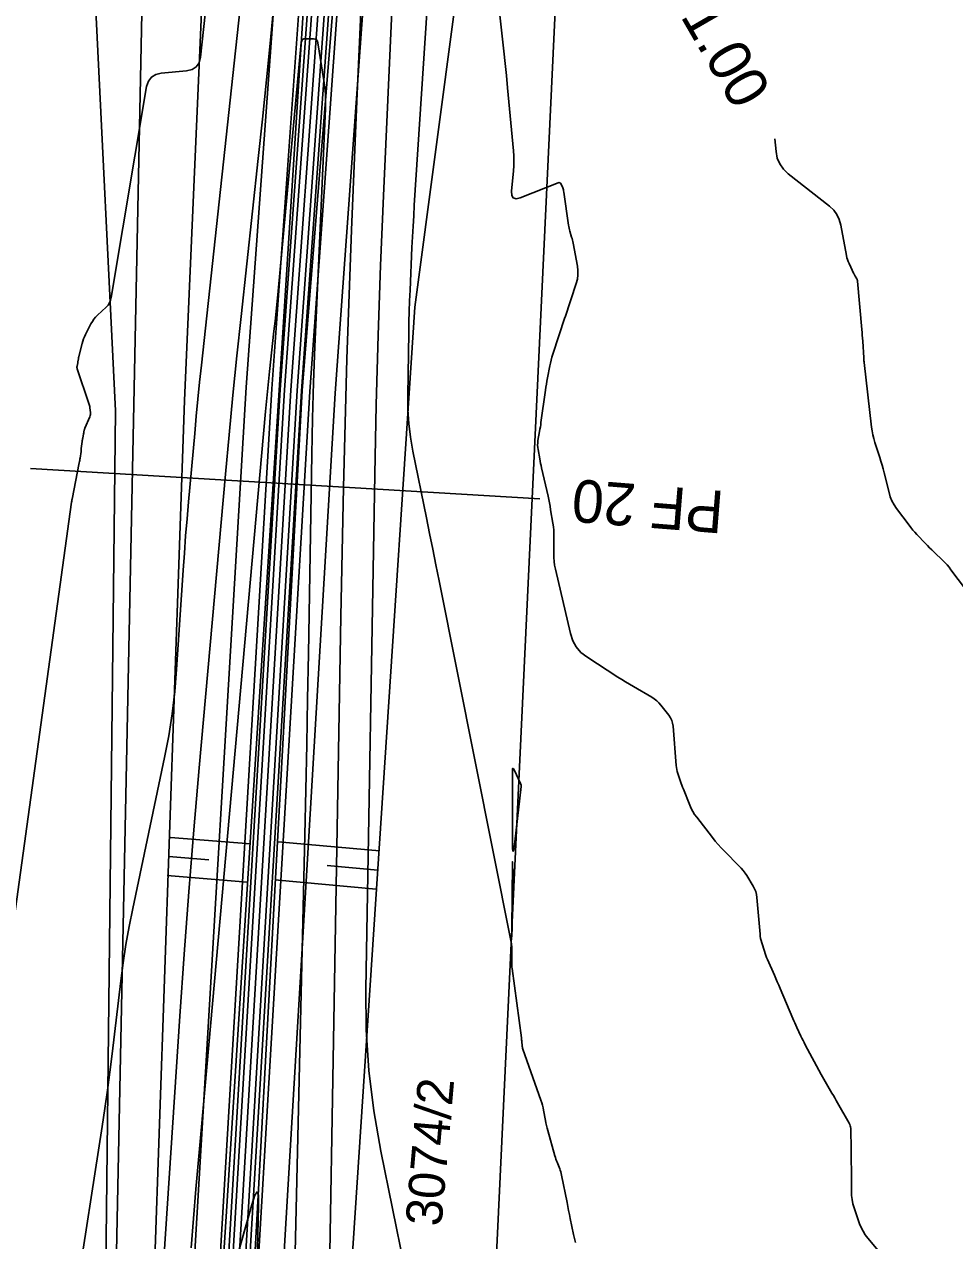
# Model space of a CAD drawing. Extents: x -534410 to -534262, y -1190162 to -1189584.
# Drawn here: x -534369.46 to -534347.57, y -1189673.55 to -1189644.95 of the extents above; entities that cross this region are included whole.
import ezdxf

# ---------------------------------------------------------------- set-up
doc = ezdxf.new("R2010")
doc.units = 0
for name, color, linetype in [('30', 7, 'Continuous'), ('31', 7, 'Continuous'), ('40', 7, 'Continuous'), ('_linie', 7, 'Continuous'), ('_N_osa', 7, 'Continuous'), ('_N_tenká', 7, 'Continuous'), ('_N_tenká_velmi', 7, 'Continuous'), ('_N_text', 7, 'Continuous'), ('_tenka', 7, 'Continuous'), ('_velmi_tenka', 7, 'Continuous'), ('Default', 7, 'Continuous'), ('Hranice parcel', 7, 'Continuous'), ('Parcelní čísla', 7, 'Continuous')]:
    doc.layers.add(name, color=color, linetype=linetype)

msp = doc.modelspace()

# ---------------------------------------------------------------- linework, layer by layer
at = {"layer": '30'}
for points in [[(-534362.459, -1189684.707), (-534362.015, -1189658.872), (-534361.953, -1189655.843), (-534361.869, -1189652.815), (-534361.764, -1189649.788), (-534361.638, -1189646.761), (-534360.829, -1189628.817)], [(-534362.766, -1189635.716), (-534363.58, -1189644.397), (-534363.668, -1189645.326), (-534363.76, -1189646.254), (-534363.856, -1189647.182), (-534363.955, -1189648.109), (-534364.357, -1189651.819), (-534364.456, -1189652.746), (-534364.55, -1189653.674), (-534364.64, -1189654.602), (-534364.726, -1189655.531), (-534365.346, -1189662.432), (-534365.472, -1189663.892), (-534365.591, -1189665.352), (-534365.7, -1189666.814), (-534365.801, -1189668.276), (-534366.596, -1189680.297)], [(-534359.474, -1189636.822), (-534360.283, -1189649.202), (-534360.298, -1189649.452), (-534360.313, -1189649.701), (-534360.326, -1189649.951), (-534360.338, -1189650.201), (-534360.383, -1189651.2), (-534360.393, -1189651.45), (-534360.402, -1189651.7), (-534360.409, -1189651.95), (-534360.414, -1189652.2), (-534360.439, -1189653.68), (-534360.436, -1189654.009), (-534360.415, -1189654.336), (-534360.376, -1189654.662), (-534360.319, -1189654.986), (-534360, -1189656.556), (-534359.925, -1189656.925), (-534359.851, -1189657.294), (-534359.776, -1189657.664), (-534359.702, -1189658.033), (-534358.003, -1189666.536), (-534357.998, -1189666.566), (-534357.994, -1189666.597), (-534357.991, -1189666.628), (-534357.99, -1189666.659), (-534357.989, -1189666.783), (-534357.989, -1189666.814), (-534357.989, -1189666.845), (-534357.989, -1189666.875), (-534357.989, -1189666.906), (-534357.99, -1189667.03), (-534357.99, -1189667.061), (-534357.988, -1189667.092), (-534357.986, -1189667.122), (-534357.982, -1189667.153), (-534357.765, -1189668.784), (-534357.762, -1189668.806), (-534357.76, -1189668.828), (-534357.757, -1189668.85), (-534357.755, -1189668.873), (-534357.747, -1189668.961), (-534357.744, -1189668.983), (-534357.74, -1189669.005), (-534357.735, -1189669.026), (-534357.728, -1189669.047), (-534357.305, -1189670.251), (-534357.285, -1189670.308), (-534357.269, -1189670.367), (-534357.254, -1189670.426), (-534357.242, -1189670.485), (-534357.197, -1189670.725), (-534357.186, -1189670.784), (-534357.173, -1189670.844), (-534357.158, -1189670.903), (-534357.142, -1189670.962), (-534356.977, -1189671.555), (-534356.965, -1189671.593), (-534356.953, -1189671.632), (-534356.939, -1189671.67), (-534356.924, -1189671.708), (-534356.863, -1189671.859), (-534356.849, -1189671.897), (-534356.837, -1189671.935), (-534356.826, -1189671.974), (-534356.817, -1189672.014), (-534356.69, -1189672.656), (-534356.672, -1189672.75), (-534356.653, -1189672.844), (-534356.633, -1189672.939), (-534356.614, -1189673.033), (-534356.535, -1189673.409), (-534356.514, -1189673.503), (-534356.489, -1189673.595)], [(-534370.511, -1189671.838), (-534368.346, -1189656.186), (-534368.343, -1189656.163), (-534368.34, -1189656.14), (-534368.339, -1189656.129), (-534368.337, -1189656.117), (-534368.167, -1189655.26), (-534368.161, -1189655.232), (-534368.156, -1189655.205), (-534368.151, -1189655.177), (-534368.147, -1189655.15), (-534368.122, -1189654.995), (-534368.121, -1189654.984), (-534368.12, -1189654.973), (-534368.12, -1189654.95), (-534368.119, -1189654.939), (-534368.118, -1189654.928), (-534368.096, -1189654.761), (-534368.094, -1189654.74), (-534368.091, -1189654.72), (-534368.087, -1189654.7), (-534368.084, -1189654.68), (-534368.066, -1189654.581), (-534368.061, -1189654.558), (-534368.057, -1189654.536), (-534368.047, -1189654.49), (-534368.044, -1189654.479), (-534368.041, -1189654.468), (-534368.037, -1189654.457), (-534368.033, -1189654.446), (-534367.919, -1189654.177), (-534367.911, -1189654.152), (-534367.905, -1189654.127), (-534367.903, -1189654.101), (-534367.904, -1189654.075), (-534367.916, -1189653.968), (-534367.919, -1189653.941), (-534367.924, -1189653.915), (-534367.931, -1189653.889), (-534367.939, -1189653.864), (-534368.214, -1189653.052), (-534368.218, -1189653.036), (-534368.22, -1189653.02), (-534368.22, -1189653.004), (-534368.218, -1189652.987), (-534368.202, -1189652.913), (-534368.2, -1189652.9), (-534368.198, -1189652.888), (-534368.196, -1189652.875), (-534368.194, -1189652.862), (-534368.187, -1189652.811), (-534368.185, -1189652.798), (-534368.183, -1189652.786), (-534368.18, -1189652.773), (-534368.177, -1189652.761), (-534368.099, -1189652.457), (-534368.083, -1189652.402), (-534368.065, -1189652.349), (-534368.043, -1189652.297), (-534368.019, -1189652.246), (-534367.891, -1189651.996), (-534367.858, -1189651.939), (-534367.822, -1189651.886), (-534367.781, -1189651.836), (-534367.735, -1189651.789), (-534367.534, -1189651.6), (-534367.489, -1189651.551), (-534367.454, -1189651.497), (-534367.428, -1189651.437), (-534367.412, -1189651.373), (-534366.581, -1189646.417), (-534366.541, -1189646.287), (-534366.47, -1189646.191), (-534366.368, -1189646.128), (-534366.236, -1189646.098), (-534365.644, -1189646.047), (-534365.512, -1189646.017), (-534365.414, -1189645.953), (-534365.348, -1189645.856), (-534365.316, -1189645.725), (-534364.406, -1189637.346)], [(-534351.799, -1189647.64), (-534351.772, -1189647.94), (-534351.743, -1189648.095), (-534351.686, -1189648.235), (-534351.6, -1189648.359), (-534351.485, -1189648.468), (-534350.515, -1189649.229), (-534350.417, -1189649.32), (-534350.34, -1189649.425), (-534350.284, -1189649.542), (-534350.248, -1189649.671), (-534350.118, -1189650.39), (-534350.107, -1189650.438), (-534350.093, -1189650.485), (-534350.076, -1189650.532), (-534350.056, -1189650.577), (-534349.939, -1189650.815), (-534349.931, -1189650.83), (-534349.924, -1189650.844), (-534349.916, -1189650.859), (-534349.908, -1189650.874), (-534349.876, -1189650.932), (-534349.868, -1189650.947), (-534349.863, -1189650.962), (-534349.859, -1189650.978), (-534349.856, -1189650.994), (-534349.755, -1189652.126), (-534349.749, -1189652.194), (-534349.744, -1189652.262), (-534349.739, -1189652.331), (-534349.734, -1189652.399), (-534349.71, -1189652.791), (-534349.709, -1189652.81), (-534349.707, -1189652.829), (-534349.704, -1189652.867), (-534349.702, -1189652.886), (-534349.7, -1189652.904), (-534349.525, -1189654.42), (-534349.512, -1189654.512), (-534349.495, -1189654.603), (-534349.473, -1189654.693), (-534349.446, -1189654.782), (-534349.332, -1189655.136), (-534349.304, -1189655.225), (-534349.278, -1189655.314), (-534349.253, -1189655.404), (-534349.23, -1189655.494), (-534349.115, -1189655.96), (-534349.085, -1189656.061), (-534349.046, -1189656.157), (-534348.996, -1189656.249), (-534348.938, -1189656.336), (-534348.644, -1189656.729), (-534348.6, -1189656.786), (-534348.554, -1189656.842), (-534348.507, -1189656.896), (-534348.458, -1189656.949), (-534348.259, -1189657.157), (-534348.209, -1189657.209), (-534348.159, -1189657.26), (-534348.107, -1189657.311), (-534348.056, -1189657.361), (-534347.847, -1189657.559), (-534347.796, -1189657.61), (-534347.748, -1189657.663), (-534347.701, -1189657.718), (-534347.657, -1189657.774), (-534347.317, -1189658.234)], [(-534364.158, -1189681.827), (-534363.949, -1189672.734), (-534363.953, -1189672.49), (-534363.981, -1189672.405), (-534364.033, -1189672.478), (-534364.11, -1189672.71), (-534364.625, -1189674.537)]]:
    msp.add_lwpolyline(points, dxfattribs=at)
for points in [[(-534357.766, -1189662.872), (-534357.766, -1189662.867), (-534357.766, -1189662.861), (-534357.766, -1189662.85), (-534357.767, -1189662.845), (-534357.768, -1189662.839), (-534357.776, -1189662.818), (-534357.779, -1189662.809), (-534357.783, -1189662.8), (-534357.926, -1189662.495), (-534357.948, -1189662.456), (-534357.963, -1189662.445), (-534357.972, -1189662.462), (-534357.975, -1189662.506), (-534357.974, -1189664.174), (-534357.971, -1189664.339), (-534357.961, -1189664.395), (-534357.945, -1189664.341), (-534357.922, -1189664.177)], [(-534357.967, -1189665.095), (-534357.967, -1189665.068), (-534357.967, -1189665.04), (-534357.967, -1189665.012), (-534357.968, -1189664.9), (-534357.968, -1189664.872), (-534357.969, -1189664.845), (-534357.969, -1189664.817), (-534357.97, -1189664.789), (-534357.972, -1189664.671), (-534357.973, -1189664.65), (-534357.974, -1189664.643), (-534357.974, -1189664.65), (-534357.974, -1189664.671), (-534357.988, -1189666.214), (-534357.989, -1189666.358), (-534357.989, -1189666.406), (-534357.987, -1189666.358), (-534357.985, -1189666.214), (-534357.967, -1189665.123)]]:
    msp.add_lwpolyline(points, close=True, dxfattribs=at)
at = {"layer": '31'}
for points in [[(-534360.41, -1189636.76), (-534360.47, -1189637.715), (-534360.553, -1189639.153), (-534360.629, -1189640.593), (-534360.697, -1189642.032), (-534361.011, -1189648.981), (-534361.079, -1189650.619), (-534361.135, -1189652.258), (-534361.181, -1189653.897), (-534361.215, -1189655.536), (-534361.422, -1189667.638), (-534361.413, -1189668.597), (-534361.351, -1189669.551), (-534361.238, -1189670.5), (-534361.072, -1189671.445), (-534359.975, -1189676.838)], [(-534349.208, -1189673.978), (-534349.616, -1189673.492), (-534349.675, -1189673.414), (-534349.727, -1189673.331), (-534349.771, -1189673.244), (-534349.807, -1189673.152), (-534349.935, -1189672.777), (-534349.963, -1189672.682), (-534349.983, -1189672.586), (-534349.996, -1189672.489), (-534350, -1189672.39), (-534350.009, -1189671.178), (-534350.01, -1189671.145), (-534350.01, -1189671.111), (-534350.011, -1189671.078), (-534350.012, -1189671.045), (-534350.017, -1189670.911), (-534350.02, -1189670.878), (-534350.027, -1189670.847), (-534350.038, -1189670.816), (-534350.053, -1189670.787), (-534350.328, -1189670.307), (-534350.36, -1189670.252), (-534350.392, -1189670.196), (-534350.424, -1189670.141), (-534350.457, -1189670.085), (-534350.587, -1189669.864), (-534350.619, -1189669.808), (-534350.651, -1189669.753), (-534350.682, -1189669.696), (-534350.712, -1189669.64), (-534351.085, -1189668.945), (-534351.112, -1189668.894), (-534351.138, -1189668.844), (-534351.163, -1189668.793), (-534351.187, -1189668.741), (-534351.283, -1189668.535), (-534351.307, -1189668.484), (-534351.33, -1189668.432), (-534351.353, -1189668.38), (-534351.376, -1189668.328), (-534351.677, -1189667.621), (-534351.71, -1189667.543), (-534351.744, -1189667.465), (-534351.777, -1189667.387), (-534351.812, -1189667.31), (-534351.975, -1189666.94), (-534351.995, -1189666.892), (-534352.014, -1189666.843), (-534352.032, -1189666.795), (-534352.048, -1189666.745), (-534352.11, -1189666.546), (-534352.124, -1189666.496), (-534352.135, -1189666.446), (-534352.144, -1189666.395), (-534352.15, -1189666.343), (-534352.224, -1189665.482), (-534352.234, -1189665.411), (-534352.252, -1189665.343), (-534352.278, -1189665.277), (-534352.312, -1189665.214), (-534352.464, -1189664.968), (-534352.503, -1189664.907), (-534352.546, -1189664.85), (-534352.592, -1189664.794), (-534352.642, -1189664.742), (-534352.988, -1189664.39), (-534353.062, -1189664.314), (-534353.133, -1189664.235), (-534353.202, -1189664.154), (-534353.269, -1189664.072), (-534353.64, -1189663.597), (-534353.689, -1189663.529), (-534353.733, -1189663.459), (-534353.771, -1189663.386), (-534353.804, -1189663.31), (-534353.952, -1189662.936), (-534353.97, -1189662.89), (-534353.987, -1189662.844), (-534354.004, -1189662.798), (-534354.02, -1189662.752), (-534354.083, -1189662.566), (-534354.098, -1189662.519), (-534354.109, -1189662.472), (-534354.117, -1189662.424), (-534354.123, -1189662.375), (-534354.197, -1189661.457), (-534354.208, -1189661.385), (-534354.228, -1189661.318), (-534354.259, -1189661.254), (-534354.299, -1189661.194), (-534354.481, -1189660.961), (-534354.529, -1189660.905), (-534354.581, -1189660.855), (-534354.638, -1189660.81), (-534354.699, -1189660.77), (-534355.127, -1189660.521), (-534355.219, -1189660.467), (-534355.311, -1189660.411), (-534355.402, -1189660.355), (-534355.492, -1189660.298), (-534356.224, -1189659.826), (-534356.363, -1189659.718), (-534356.473, -1189659.591), (-534356.556, -1189659.444), (-534356.611, -1189659.278), (-534356.965, -1189657.76), (-534356.983, -1189657.67), (-534356.995, -1189657.58), (-534357.002, -1189657.489), (-534357.004, -1189657.397), (-534356.998, -1189657.007), (-534356.998, -1189656.926), (-534357.002, -1189656.845), (-534357.01, -1189656.765), (-534357.022, -1189656.684), (-534357.076, -1189656.364), (-534357.09, -1189656.284), (-534357.105, -1189656.205), (-534357.121, -1189656.125), (-534357.138, -1189656.046), (-534357.288, -1189655.382), (-534357.3, -1189655.328), (-534357.311, -1189655.275), (-534357.322, -1189655.221), (-534357.332, -1189655.167), (-534357.373, -1189654.951), (-534357.38, -1189654.898), (-534357.383, -1189654.844), (-534357.381, -1189654.791), (-534357.374, -1189654.738), (-534357.336, -1189654.525), (-534357.327, -1189654.472), (-534357.318, -1189654.419), (-534357.31, -1189654.365), (-534357.303, -1189654.312), (-534357.199, -1189653.55), (-534357.189, -1189653.479), (-534357.177, -1189653.409), (-534357.165, -1189653.338), (-534357.152, -1189653.267), (-534357.097, -1189652.985), (-534357.083, -1189652.915), (-534357.066, -1189652.846), (-534357.046, -1189652.777), (-534357.025, -1189652.708), (-534356.741, -1189651.848), (-534356.737, -1189651.837), (-534356.475, -1189651.042), (-534356.448, -1189650.943), (-534356.435, -1189650.843), (-534356.435, -1189650.742), (-534356.448, -1189650.64), (-534356.549, -1189650.097), (-534356.556, -1189650.061), (-534356.564, -1189650.025), (-534356.573, -1189649.99), (-534356.583, -1189649.955), (-534356.623, -1189649.815), (-534356.633, -1189649.78), (-534356.641, -1189649.745), (-534356.648, -1189649.709), (-534356.654, -1189649.673), (-534356.767, -1189648.894), (-534356.771, -1189648.869), (-534356.777, -1189648.845), (-534356.785, -1189648.822), (-534356.793, -1189648.799), (-534356.832, -1189648.707), (-534356.843, -1189648.688), (-534356.858, -1189648.677), (-534356.876, -1189648.674), (-534356.897, -1189648.68), (-534357.792, -1189649.03), (-534357.888, -1189649.053), (-534357.954, -1189649.035), (-534357.989, -1189648.977), (-534357.994, -1189648.878), (-534357.952, -1189648.4), (-534357.944, -1189648.281), (-534357.941, -1189648.162), (-534357.944, -1189648.042), (-534357.953, -1189647.923), (-534358.089, -1189646.444), (-534358.116, -1189646.158), (-534358.144, -1189645.872), (-534358.174, -1189645.586), (-534358.205, -1189645.301), (-534358.606, -1189641.691)], [(-534368.867, -1189678.859), (-534367.627, -1189670.868), (-534367.562, -1189670.442), (-534367.502, -1189670.014), (-534367.445, -1189669.587), (-534367.392, -1189669.158), (-534367.188, -1189667.444), (-534367.132, -1189667.016), (-534367.067, -1189666.59), (-534366.992, -1189666.165), (-534366.908, -1189665.742), (-534366.16, -1189662.191), (-534366.061, -1189661.677), (-534365.981, -1189661.16), (-534365.919, -1189660.641), (-534365.875, -1189660.119), (-534365.721, -1189657.786), (-534365.693, -1189657.383), (-534365.663, -1189656.981), (-534365.63, -1189656.579), (-534365.595, -1189656.177), (-534365.451, -1189654.569), (-534365.414, -1189654.167), (-534365.375, -1189653.765), (-534365.334, -1189653.364), (-534365.291, -1189652.963), (-534364.324, -1189644.049)], [(-534365.532, -1189673.723), (-534365.42, -1189672.34), (-534365.3, -1189670.958), (-534363.781, -1189654.053), (-534363.759, -1189653.817), (-534363.737, -1189653.581), (-534363.713, -1189653.346), (-534363.688, -1189653.111), (-534363.586, -1189652.17), (-534363.56, -1189651.934), (-534363.536, -1189651.699), (-534363.513, -1189651.463), (-534363.49, -1189651.228), (-534362.943, -1189645.379), (-534362.933, -1189645.339), (-534362.913, -1189645.311), (-534362.883, -1189645.294), (-534362.842, -1189645.289), (-534362.659, -1189645.292), (-534362.618, -1189645.299), (-534362.586, -1189645.316), (-534362.565, -1189645.345), (-534362.553, -1189645.385), (-534362.411, -1189646.272), (-534362.389, -1189646.435), (-534362.375, -1189646.599), (-534362.37, -1189646.763), (-534362.374, -1189646.928), (-534362.588, -1189651.678), (-534362.623, -1189652.524), (-534362.652, -1189653.371), (-534362.676, -1189654.218), (-534362.693, -1189655.065), (-534362.774, -1189659.756), (-534362.793, -1189660.82), (-534362.813, -1189661.885), (-534362.835, -1189662.949), (-534362.859, -1189664.013), (-534363.288, -1189682.613)]]:
    msp.add_lwpolyline(points, dxfattribs=at)
at = {"layer": '_linie'}
for points in [[(-534366.12, -1189620.81), (-534364.52, -1189627.2), (-534365.69, -1189653.8), (-534366.76, -1189684.81), (-534368.14, -1189748.73), (-534368.38, -1189779.14), (-534368.65, -1189820.64), (-534368.59, -1189847.58), (-534367.2, -1189913.8)], [(-534363.12, -1189621.02), (-534362.79, -1189621.58), (-534361.82, -1189627.79), (-534363.46, -1189653.55), (-534365.47, -1189684.77), (-534366.65, -1189748.83), (-534366.75, -1189779.47), (-534366.9, -1189820.47), (-534366.95, -1189846.72), (-534366.338, -1189888.804), (-534363.85, -1189911.95), (-534357.07, -1189929.19), (-534352.334, -1189940.856)], [(-534359.03, -1189621.26), (-534359.41, -1189621.83), (-534360.84, -1189627.76), (-534362.92, -1189653.56), (-534364.64, -1189685), (-534365.94, -1189748.9), (-534366.02, -1189779.52), (-534366.03, -1189820.5), (-534366.48, -1189846.73), (-534365.511, -1189888.873), (-534362.72, -1189912.12), (-534356.62, -1189928.64), (-534351.589, -1189940.594)]]:
    msp.add_lwpolyline(points, dxfattribs=at)
at = {"layer": '_N_osa'}
msp.add_lwpolyline([(-534351.95, -1189940.722), (-534356.845, -1189928.915), (-534363.285, -1189912.035), (-534365.925, -1189888.838), (-534366.715, -1189846.725), (-534366.465, -1189820.485), (-534366.385, -1189779.495), (-534366.295, -1189748.865), (-534365.055, -1189684.885), (-534363.19, -1189653.555), (-534361.333, -1189627.822)], dxfattribs=at)
at = {"layer": '_N_tenká'}
for points in [[(-534352.92, -1189941.124), (-534357.821, -1189929.303), (-534364.313, -1189912.285), (-534366.973, -1189888.908), (-534367.765, -1189846.73), (-534367.515, -1189820.479), (-534367.435, -1189779.492), (-534367.345, -1189748.853), (-534366.104, -1189684.844), (-534364.238, -1189653.486), (-534362.424, -1189628.352), (-534361.782, -1189627.792)], [(-534352.089, -1189940.779), (-534356.984, -1189928.97), (-534363.432, -1189912.071), (-534366.074, -1189888.848), (-534366.865, -1189846.726), (-534366.615, -1189820.484), (-534366.535, -1189779.495), (-534366.445, -1189748.863), (-534365.205, -1189684.879), (-534363.34, -1189653.545), (-534361.483, -1189627.812)], [(-534351.812, -1189940.664), (-534356.706, -1189928.86), (-534363.138, -1189911.999), (-534365.775, -1189888.828), (-534366.565, -1189846.724), (-534366.315, -1189820.486), (-534366.235, -1189779.495), (-534366.145, -1189748.867), (-534364.905, -1189684.891), (-534363.04, -1189653.565), (-534361.184, -1189627.831)], [(-534350.98, -1189940.319), (-534355.869, -1189928.527), (-534362.257, -1189911.785), (-534364.876, -1189888.769), (-534365.665, -1189846.72), (-534365.415, -1189820.491), (-534365.335, -1189779.498), (-534365.245, -1189748.877), (-534364.006, -1189684.926), (-534362.142, -1189653.624), (-534360.329, -1189628.488), (-534360.884, -1189627.851)]]:
    msp.add_lwpolyline(points, dxfattribs=at)
at = {"layer": '_N_tenká_velmi'}
for points in [[(-534352.366, -1189940.894), (-534357.263, -1189929.081), (-534363.726, -1189912.142), (-534366.374, -1189888.868), (-534367.165, -1189846.727), (-534366.915, -1189820.482), (-534366.835, -1189779.494), (-534366.745, -1189748.86), (-534365.505, -1189684.867), (-534363.639, -1189653.525), (-534361.782, -1189627.792)], [(-534352.181, -1189940.817), (-534357.077, -1189929.007), (-534363.53, -1189912.095), (-534366.174, -1189888.855), (-534366.965, -1189846.726), (-534366.715, -1189820.484), (-534366.635, -1189779.494), (-534366.545, -1189748.862), (-534365.305, -1189684.875), (-534363.439, -1189653.539), (-534361.583, -1189627.805)], [(-534351.719, -1189940.626), (-534356.613, -1189928.823), (-534363.04, -1189911.975), (-534365.675, -1189888.822), (-534366.465, -1189846.724), (-534366.215, -1189820.486), (-534366.135, -1189779.496), (-534366.045, -1189748.868), (-534364.805, -1189684.895), (-534362.941, -1189653.571), (-534361.084, -1189627.838)], [(-534351.534, -1189940.549), (-534356.427, -1189928.749), (-534362.844, -1189911.928), (-534365.475, -1189888.808), (-534366.265, -1189846.723), (-534366.015, -1189820.488), (-534365.935, -1189779.496), (-534365.845, -1189748.87), (-534364.605, -1189684.903), (-534362.741, -1189653.585), (-534360.884, -1189627.851)]]:
    msp.add_lwpolyline(points, dxfattribs=at)
at = {"layer": '_N_text'}
msp.add_lwpolyline([(-534357.331, -1189656.108), (-534369.31, -1189655.395)], dxfattribs=at)
at = {"layer": '_tenka'}
for points in [[(-534349.13, -1189939.73), (-534354.63, -1189926.96), (-534362.03, -1189907.65), (-534364.521, -1189888.74), (-534364.47, -1189846.64), (-534364.29, -1189820.63), (-534364.22, -1189780.69), (-534363.18, -1189749.38), (-534362.5, -1189685.39), (-534360.27, -1189651.6), (-534357.03, -1189627.34), (-534354.77, -1189620.37)], [(-534366.12, -1189620.81), (-534364.52, -1189627.2), (-534365.69, -1189653.8), (-534366.76, -1189684.81), (-534368.14, -1189748.73), (-534368.38, -1189779.14), (-534368.65, -1189820.64), (-534368.59, -1189847.58), (-534367.2, -1189913.8)], [(-534366.12, -1189620.81), (-534364.52, -1189627.2), (-534365.69, -1189653.8), (-534366.76, -1189684.81), (-534368.14, -1189748.73), (-534368.38, -1189779.14), (-534368.65, -1189820.64), (-534368.59, -1189847.58), (-534367.2, -1189913.8)], [(-534363.12, -1189621.02), (-534362.79, -1189621.58), (-534361.82, -1189627.79), (-534363.46, -1189653.55), (-534365.47, -1189684.77), (-534366.65, -1189748.83), (-534366.75, -1189779.47), (-534366.9, -1189820.47), (-534366.95, -1189846.72), (-534366.338, -1189888.804), (-534363.85, -1189911.95), (-534357.07, -1189929.19), (-534352.334, -1189940.856)], [(-534363.12, -1189621.02), (-534362.79, -1189621.58), (-534361.82, -1189627.79), (-534363.46, -1189653.55), (-534365.47, -1189684.77), (-534366.65, -1189748.83), (-534366.75, -1189779.47), (-534366.9, -1189820.47), (-534366.95, -1189846.72), (-534366.338, -1189888.804), (-534363.85, -1189911.95), (-534357.07, -1189929.19), (-534352.334, -1189940.856)], [(-534359.03, -1189621.26), (-534359.41, -1189621.83), (-534360.84, -1189627.76), (-534362.92, -1189653.56), (-534364.64, -1189685), (-534365.94, -1189748.9), (-534366.02, -1189779.52), (-534366.03, -1189820.5), (-534366.48, -1189846.73), (-534365.511, -1189888.873), (-534362.72, -1189912.12), (-534356.62, -1189928.64), (-534351.589, -1189940.594)], [(-534359.03, -1189621.26), (-534359.41, -1189621.83), (-534360.84, -1189627.76), (-534362.92, -1189653.56), (-534364.64, -1189685), (-534365.94, -1189748.9), (-534366.02, -1189779.52), (-534366.03, -1189820.5), (-534366.48, -1189846.73), (-534365.511, -1189888.873), (-534362.72, -1189912.12), (-534356.62, -1189928.64), (-534351.589, -1189940.594)], [(-534368.65, -1189626.81), (-534368.65, -1189626.81), (-534367.31, -1189654.04), (-534367.67, -1189685.23), (-534369.56, -1189748.93), (-534369.48, -1189778.6), (-534369.45, -1189820.62), (-534369.45, -1189847.87), (-534371.206, -1189896.071), (-534372.39, -1189914.47)]]:
    msp.add_lwpolyline(points, dxfattribs=at)
at = {"layer": '_velmi_tenka'}
for p, q in [((-534366.023, -1189664.069), (-534364.139, -1189664.224)), ((-534361.103, -1189664.388), (-534363.484, -1189664.171)), ((-534366.06, -1189664.517), (-534365.118, -1189664.595)), ((-534366.097, -1189664.965), (-534364.213, -1189665.121)), ((-534361.144, -1189664.836), (-534362.334, -1189664.728)), ((-534361.184, -1189665.284), (-534363.566, -1189665.067))]:
    msp.add_line(p, q, dxfattribs=at)
at = {"layer": 'Default'}
for p, q in [((-534368.65, -1189626.81), (-534367.31, -1189654.04)), ((-534367.31, -1189654.04), (-534367.67, -1189685.23))]:
    msp.add_line(p, q, dxfattribs=at)
msp.add_lwpolyline([(-534349.13, -1189939.73), (-534354.63, -1189926.96), (-534362.03, -1189907.65), (-534364.521, -1189888.74), (-534364.47, -1189846.64), (-534364.29, -1189820.63), (-534364.22, -1189780.69), (-534363.18, -1189749.38), (-534362.5, -1189685.39), (-534360.27, -1189651.6), (-534357.03, -1189627.34), (-534354.77, -1189620.37)], dxfattribs=at)
at = {"layer": 'Hranice parcel'}
for p, q in [((-534359.48, -1189697.97), (-534356.61, -1189636.93)), ((-534366.56, -1189638.19), (-534367.77, -1189697.34))]:
    msp.add_line(p, q, dxfattribs=at)

# ---------------------------------------------------------------- texts
at = {"layer": '40'}
msp.add_text('231.00', height=1, rotation=300.0371, dxfattribs=at).set_placement((-534354.779, -1189643.469))
at = {"layer": '_N_text'}
msp.add_text('PF 20', height=1, rotation=175.4144, dxfattribs=at).set_placement((-534352.97, -1189655.929))
at = {"layer": 'Parcelní čísla'}
msp.add_text('3074/2', height=0.85, rotation=85, dxfattribs=at).set_placement((-534359.647, -1189673.232))

doc.saveas('drawing.dxf')
